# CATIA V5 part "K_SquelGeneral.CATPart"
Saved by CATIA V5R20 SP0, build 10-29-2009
Part number: Squelette General
Publications: "Longueur_bati", "Longueur_bielle_motrice", "Distance_bati_mors", "Demi_largeur_bati_axe_1", "Plan_Ref", "Point.1", "Point.2", "Point.3", "Point.4", "Point.5", "Point.6", "Point.7", "Point.8", "Point.9", "Point.10", "Point.11", "Point.12"
Bounding box of the stored display mesh (mm): x -650 to 0, y 0 to 0, z -180 to 180
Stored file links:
  G:\Khaled_CFAO_2011\ST2M\ST2M_GR2\jcoetard\Khaled\CAD_CATIA\K_SquelGeneral.CATPart
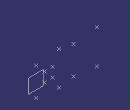
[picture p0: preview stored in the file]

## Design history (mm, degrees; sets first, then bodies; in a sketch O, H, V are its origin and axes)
Parameters
  Longueur_bati = 250 mm
  Longueur_bielle_motrice = 90 mm
  Distance_bati_mors = 150 mm
  Demi_largeur_bati_axe_1 = 150 mm
  Hauteur_bati_axe_2 = 180 mm {= Demi_largeur_bati_axe_1 + 30 mm}
  Hauteur_mors_axe_1 = 150 mm {= Demi_largeur_bati_axe_1}
  Hauteur_mors_axe_2 = 180 mm {= Hauteur_bati_axe_2}
  `Hauteur_écrou` = 50 mm {= Demi_largeur_bati_axe_1 / 3}
Set1 "Set géométrique"
  Plane1 "Plan_Ref": type Offset, RefPlane zx-plane, Offset 0
  Point1: (0, 0, 150 {= Demi_largeur_bati_axe_1})
  Point2: (-250 {= -Longueur_bati}, 0, 180 {= Hauteur_bati_axe_2})
  Point3: (-400 {= -(Longueur_bati + Distance_bati_mors)}, 0, 150 {= Hauteur_mors_axe_1})
  Point4: (-650 {= -(2*Longueur_bati + Distance_bati_mors)}, 0, 180 {= Hauteur_mors_axe_2})
  Point5: (-180 {= -2*Longueur_bielle_motrice}, 0, 50 {= `Hauteur_écrou`})
  Point6: (-90 {= -Longueur_bielle_motrice}, 0, 50 {= `Hauteur_écrou`})
  Point7: (0, 0, -150 {= -Demi_largeur_bati_axe_1})
  Point8 "Point.8": (-250 {= -Longueur_bati}, 0, -180 {= -Hauteur_bati_axe_2})
  Point9 "Point.9": (-400 {= -(Longueur_bati + Distance_bati_mors)}, 0, -150 {= -Hauteur_mors_axe_1})
  Point10 "Point.10": (-650 {= -(2*Longueur_bati + Distance_bati_mors)}, 0, -180 {= -Hauteur_mors_axe_2})
  Point11 "Point.11": (-90 {= -Longueur_bielle_motrice}, 0, -50 {= -`Hauteur_écrou`})
  Point12 "Point.12": (-180 {= -2*Longueur_bielle_motrice}, 0, -50 {= -`Hauteur_écrou`})
Body1 (main body)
